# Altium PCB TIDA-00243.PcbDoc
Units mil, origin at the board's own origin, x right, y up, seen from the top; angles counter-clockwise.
Board outline 354.33 x 511.81 mil, 4 copper layers (Top Layer, MidLayer1, MidLayer2, Bottom Layer), stack 31.584 mil thick; 39 components, 21 nets, 112 pads, 89 vias.
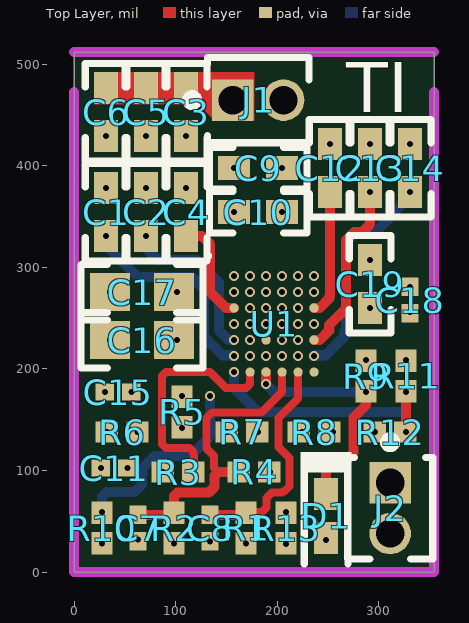
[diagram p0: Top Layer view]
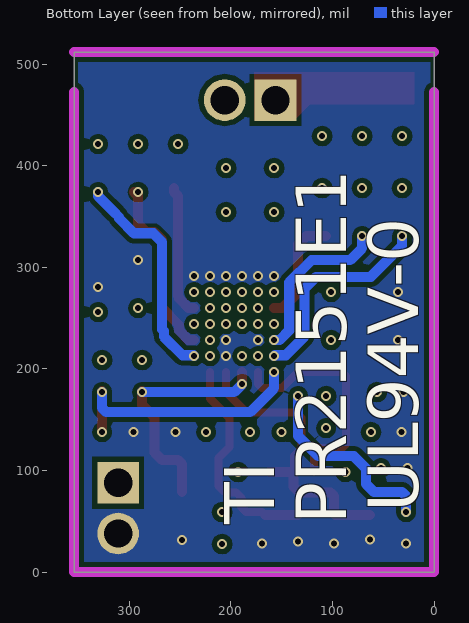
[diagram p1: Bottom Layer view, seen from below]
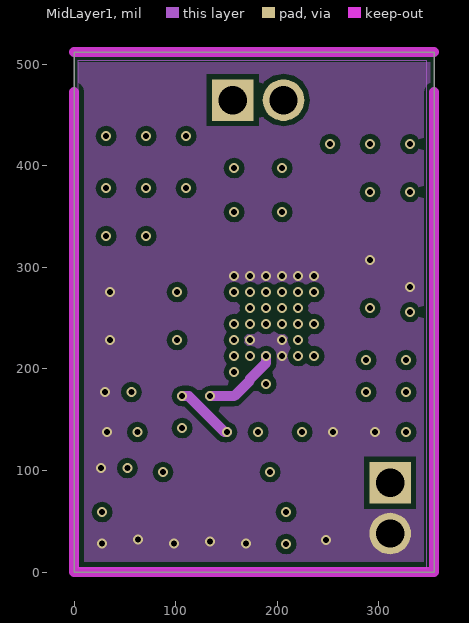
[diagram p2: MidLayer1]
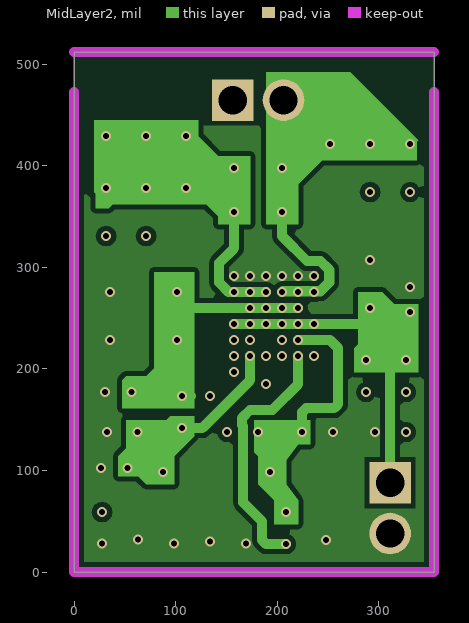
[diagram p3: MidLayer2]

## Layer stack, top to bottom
Top Layer: signal copper 1.4
Dielectric: core 8.6614, FR-4, Dk 4.8
MidLayer1: signal copper 1.4
Dielectric: prepreg 8.6614, FR-4, Dk 4.8
MidLayer2: signal copper 1.4
Dielectric: core 8.6614, FR-4, Dk 4.8
Bottom Layer: signal copper 1.4

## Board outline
0,0 0,511.81 354.33,511.81 354.33,0 0,0

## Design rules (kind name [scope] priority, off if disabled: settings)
AcuteAngle [All] p1: minimum=4.50000000000000E+0001 checktracksonly=FALSE
AssemblyTestPointUsage [All] p1: valid=2
Clearance Clearance_BoardEdge_MountingHoles [OnCopper and InComponentClass('Mounting Holes') vs IsKeepOut] p1: gap=4.92
Clearance Clearance_BoardEdge_Poly [OnCopper and InPoly vs IsKeepOut] p2: gap=4.92
Clearance Clearance_BoardEdge [OnCopper and Not InComponentClass('Logo') and not InComponentClass('FiducialMark') and not InRegion(1000,500,4000,800) and Not IsKeepout vs IsKeepOut] p3: gap=4.92
Clearance Clearance_Poly [InPolygon] p4: gap=4.92
Clearance [All] p5: gap=4.92
ComponentClearance ComponentClearance_Logo [InComponentClass('Logo')] p1: gap=4.92 collisioncheckmode=3 verticalgap=4.92 showdistances=FALSE
ComponentClearance ComponentClearance_ScrewToNut [(HasFootprint('NY PMS 440 0025 PH')) vs (HasFootprint('Keystone_1902C'))] p2: gap=4.92 collisioncheckmode=3 verticalgap=4.92 showdistances=FALSE
ComponentClearance ComponentClearance_MountingHoles [InComponentClass('Mounting Holes')] p3: gap=4.92 collisioncheckmode=3 verticalgap=100000 showdistances=FALSE
ComponentClearance ComponentClearance_SmallPassives [HasFootprint('0201*') or HasFootprint('0402*') or HasFootprint('0508') or HasFootprint('0603*') or HasFootprint('0612') or HasFootprint('0805*') or HasFootprint('0815*') or HasFootprint('0830*') or HasFootprint('1206*') or HasFootprint('1210*') or HasFootprint('1808*') or HasFootprint('1812*') or HasFootprint('1825*') or HasFootprint('2010*') or HasFootprint('2220*') or HasFootprint('2225*') or HasFootprint('2512*') or HasFootprint('2728*') or HasFootprint('3518*') vs HasFootprint('0201*') or HasFootprint('0402*') or HasFootprint('0508') or HasFootprint('0603*') or HasFootprint('0612') or HasFootprint('0805*') or HasFootprint('0815*') or HasFootprint('0830*') or HasFootprint('1206*') or HasFootprint('1210*') or HasFootprint('1808*') or HasFootprint('1812*') or HasFootprint('1825*') or HasFootprint('2010*') or HasFootprint('2220*') or HasFootprint('2225*') or HasFootprint('2512*') or HasFootprint('2728*') or HasFootprint('3518*')] p4: gap=4.92 collisioncheckmode=3 verticalgap=4.92 showdistances=FALSE
ComponentClearance ComponentClearance_THtoSMT [IsThruComponent vs IsSMTComponent] p5: gap=4.92 collisioncheckmode=3 verticalgap=4.92 showdistances=FALSE
ComponentClearance ComponentClearance_THtoTH [IsThruComponent vs IsThruComponent] p6: gap=4.92 collisioncheckmode=3 verticalgap=4.92 showdistances=FALSE
ComponentClearance [All] p7: gap=4.92 collisioncheckmode=3 verticalgap=4.92 showdistances=FALSE
DiffPairsRouting [All] p1: maxlimit=100 minlimit=10 mostfreqgap=10 maxuncoupledlength=1000
FabricationTestPointUsage TestPointUsage [All] p1: valid=2 allowmultiple=FALSE
FabricationTestpoint Testpoint [All] p1: side=3 testpointundercomponent=TRUE minsize=40 maxsize=100 preferedsize=60 minholesize=0 maxholesize=40 preferedholesize=32 testpointgrid=1 allowsidetop=TRUE allowsidebottom=TRUE usegrid=TRUE gridtolerance=0.01
FanoutControl Fanout_LCC [IsLCC] p1: bgadir=Out bgaviamode=Centered fanoutstyle=Auto fanoutdirection=Alternating viagrid=1 // Fanout_LCC (Default Rule)
FanoutControl Fanout_BGA [IsBGA] p2: bgadir=Out bgaviamode=Centered fanoutstyle=Auto fanoutdirection=Alternating viagrid=1 // Fanout_BGA (Default Rule)
FanoutControl Fanout_Default [All] p4: bgadir=Out bgaviamode=Centered fanoutstyle=Auto fanoutdirection=Alternating viagrid=1 // Fanout_Default (Default Rule)
FanoutControl Fanout_Small [(CompPinCount < 5)] p5: bgadir=Out bgaviamode=Centered fanoutstyle=Auto fanoutdirection=OutThenIn viagrid=1 // Fanout_Small (Default Rule)
HoleSize [All] p1: absolutevalues=TRUE maxlimit=251 minlimit=5 maxpercent=80.000 minpercent=20.000
HoleToHoleClearance [All] p1: gap=9 allowstackedmicrovias=TRUE
MinimumAnnularRing [All] p1: minimumring=4
MinimumSolderMaskSliver MinimumSolderMaskSliver_Logo [InComponentClass('Logo') vs InComponentClass('Logo')] p1: minsoldermaskwidth=0.7
MinimumSolderMaskSliver [All] p2: minsoldermaskwidth=4
PlaneClearance [All] p1: clearance=4.92
PlaneConnect [All] p1: planeconnectstyle=Direct reliefexpansion=10 reliefentries=4 reliefconductorwidth=10 reliefairgap=10
PolygonConnect [All] p1: connectstyle=Direct reliefconductorwidth=10 reliefentries=4 polygonreliefangle="90 Angle" airgapwidth=10
RoutingVias [All] p1: holewidth=16 width=34 viastyle="Through Hole" minholewidth=5 minwidth=9 maxholewidth=40 maxwidth=65
SMDToCorner [All] p1: distance=30000
SilkToSilkClearance [All] p1: silktosilkclearance=5
SilkscreenOverComponentPads [All] p1: minsilkscreentomaskgap=5
SolderMaskExpansion [All] p1: expansion=3
Width [All] p1: maxlimit=98.43 minlimit=4.92 preferedwidth=10 toplayer_prefwidth=7.87 midlayer1_minwidth=6 midlayer2_minwidth=6 bottomlayer_prefwidth=7.87 minimp=50.000000 maximp=50.000000 favimp=50.000000 checkconnectedcopper=TRUE
12 further rules are at their usual default settings.

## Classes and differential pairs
component class "PR2151 sheet 2": C1 C2 C3 C4 C5 C6 C7 C8 C9 C10 C11 C12 C13 C14 C15 C16 C17 C18 C19 D1 J1 J2 R1 R2 R3 R4 R5 R6 R7 R8 R9 R10 R11 R12 R13 U1
component class AssemblyNote: ZZ1 ZZ2 ZZ3
component class "PR2151 sheet 3": ZZ1 ZZ2 ZZ3

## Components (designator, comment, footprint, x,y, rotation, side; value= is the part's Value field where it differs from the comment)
C1 "C1005X7R1H683K" 0402 31.5,354.33 r90 top
C2 "UMK105ABJ474KV-F" 0402 70.87,354.33 r90 top
C3 "C1005X7R1H104K" 0402 110.24,452.76 r90 top
C4 "GRM155R71H153KA12D" 0402 110.24,354.33 r90 top
C5 "C1005X7R1H683K" 0402 70.87,452.76 r90 top
C6 "C1005X7R1H683K" 0402 31.5,452.76 r90 top
C7 "C0603X5R1E104K030BB" 0201 62.99,43.31 r270 top
C8 "CL03A105MP3NSNC" 0201 133.86,43.31 r270 top
C9 "GRM1555C1H101JA01D" 0402 181.1,397.64 r0 top
C10 "GRM155R71H272KA01J" 0402 181.1,354.33 r0 top
C11 "C0603X5R1E104K030BB" 0201 39.37,102.36 r180 top
C12 "GRM155R71H153KA12D" 0402 251.97,397.64 r90 top
C13 "UMK105ABJ474KV-F" 0402 291.34,397.64 r90 top
C14 "C1005X7R1H683K" 0402 330.71,397.64 r90 top
C15 "C0603X5R1E104K030BB" 0201 43.31,177.17 r180 top
C16 "GRM188R61E106MA73D" 0603 66.93,228.35 r180 top
C17 "GRM188R61E106MA73D" 0603 66.93,275.59 r180 top
C18 "C0603X5R1E104K030BB" 0201 330.71,267.72 r90 top
C19 "CGB2A1X5R1E105K033BC" 0402 291.34,283.46 r90 top
D1 "BZT52C5V1T-7" SOD-523 248.03,55.12 r270 top
J1 "GRPB021VWVN-RC" Sullins_GRPB021VWVN-RC 181.1,464.57 r0 top
J2 "GRPB021VWVN-RC" Sullins_GRPB021VWVN-RC 311.02,62.99 r270 top
R1 "ERJ-1GEF1004C" 0201M 169.29,43.31 r90 top
R2 "ERJ-1GEF1002C" 0201M 98.43,43.31 r90 top
R3 "ERJ-1GEF1100C" 0201M 102.36,98.43 r0 top
R4 "ERJ-1GEF2002C" 0201M 177.17,98.43 r180 top
R5 "ERJ-1GEF2002C" 0201M 106.3,157.48 r270 top
R6 "ERJ-1GEF4990C" 0201M 47.24,137.8 r0 top
R7 "ERJ-1GEF1023C" 0201M 165.35,137.8 r0 top
R8 "ERJ-1GEF1132C" 0201M 236.22,137.8 r180 top
R9 "ERJ-1GEF1002C" 0201M 287.4,192.91 r270 top
R10 "ERJ-1GEF1001C" 0201M 27.56,43.31 r90 top
R11 "ERJ-1GEF1023C" 0201M 326.77,192.91 r90 top
R12 "ERJ-1GEF1132C" 0201M 311.02,137.8 r0 top
R13 "ERJ-1GEF1132C" 0201M 208.66,43.31 r270 top
U1 "bq5102x" YFP0042AWCG 196.85,244.09 r0 top
ZZ1 "These assemblies are ESD sensitive, ESD precautions shall be observed." AssemblyNote 141.69,1242.5 r0 top
ZZ2 "These assemblies must be clean and free from flux and all contaminants. Use of no clean flux is not acceptable." AssemblyNote 141.69,1153.94 r0 top
ZZ3 "These assemblies must comply with workmanship standards IPC-A-610 Class 2., unless otherwise specified." AssemblyNote 141.69,1065.39 r0 top

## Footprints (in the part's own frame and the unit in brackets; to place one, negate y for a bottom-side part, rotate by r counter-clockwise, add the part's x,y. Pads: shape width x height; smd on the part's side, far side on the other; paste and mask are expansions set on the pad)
0201 [mm] "Data from Kemet datasheet CC101_COM dated 7/28/11"
  rect 0.46x0.42 smd mask+0.048: 1(-0.33,0) 2(0.33,0)
  body extent -0.31,-0.16 0.31,0.16, height 0.26
0201M [mm] "Data from Kemet datasheet CC101_COM dated 7/28/11"
  rect 0.56x0.52 smd mask+0.048: 1(-0.38,0) 2(0.38,0)
  body extent -0.31,-0.16 0.31,0.16, height 0.26
0402 [mm] "0402 from SM-752 data"
  rect 0.8x0.6 smd: 1(-0.6,0) 2(0.6,0)
  silkscreen extent -1.22,-0.52 1.22,0.52, body extent -0.55,-0.3 0.55,0.3, height 0.6
0603 [mm] "0603 from SM-752 data"
  rect 1x0.95 smd: 1(-0.8,0) 2(0.8,0)
  silkscreen extent -1.52,-0.69 1.52,0.69, body extent -0.87,-0.47 0.87,0.47, height 0.85
AssemblyNote [mil] "Assembly Note"
SOD-523 [mm] "NXP Semiconductor recommended land pattern, nominal STEP model"
  rect 0.8x0.6 smd paste-0.05: 1(-0.55,0) 2(0.55,0)
  silkscreen extent -1.6,-0.63 1.2,0.64, body extent -0.8,-0.4 0.8,0.4, height 0.72
Sullins_GRPB021VWVN-RC [mil] "Sullins"
  rect 41x41 hole 28: 1(-25,0)
  round 41 hole 28: 2(25,0)
  silkscreen extent -70,-42 50,42, body extent -50,-42 50,42, height 157
YFP0042AWCG [mm] "BGA, 42-Leads, Body 3.556x2.844mm,  Pitch 0.4mm"
  round 0.23 smd paste-0.2 mask+0.04: A1(-1,1.2) A2(-0.6,1.2) A3(-0.2,1.2) A4(0.2,1.2) A5(0.6,1.2) A6(1,1.2) B1(-1,0.8) B2(-0.6,0.8) B3(-0.2,0.8) B4(0.2,0.8) B5(0.6,0.8) B6(1,0.8) C1(-1,0.4) C2(-0.6,0.4) C3(-0.2,0.4) C4(0.2,0.4) C5(0.6,0.4) C6(1,0.4) D1(-1,0) D2(-0.6,0) D3(-0.2,0) D4(0.2,0) D5(0.6,0) D6(1,0) E1(-1,-0.4) E2(-0.6,-0.4) E3(-0.2,-0.4) E4(0.2,-0.4) E5(0.6,-0.4) E6(1,-0.4) F1(-1,-0.8) F2(-0.6,-0.8) F3(-0.2,-0.8) F4(0.2,-0.8) F5(0.6,-0.8) F6(1,-0.8) G1(-1,-1.2) G2(-0.6,-1.2) G3(-0.2,-1.2) G4(0.2,-1.2) G5(0.6,-1.2) G6(1,-1.2)
  silkscreen extent -1.7,1.65 -1.6,1.75, body extent -1.44,-1.8 1.44,1.8, height 0.51

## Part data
C1 C5 C6 C14: "CAP, CERM, 0.068uF, 50V, +/-10%, C0G/NP0, 0402"
C2 C13: library part GRM155R61A474KE15D, "CAP, CERM, 0.47uF, 50V, +/-10%, X5R, 0402"
C3: "CAP, CERM, 0.1uF, 50V, +/-10%, C0G/NP0, 0402"
C4 C12: "CAP, CERM, 0.015uF, 50V, +/-10%, X7R, 0402"
C7 C11 C15 C18: library part C0603X5R0J103K, "CAP, CERM, 0.1uF, 25V, +/-10%, X5R, 0201"
C8: "CAP, CERM, 1uF, 10V, +/-20%, X5R, 0201"
C9: "CAP, CERM, 100pF, 50V, +/-5%, C0G/NP0, 0402"
C10: library part GRM155R71H222KA01D, "CAP, CERM, 2700pF, 50V, +/-10%, X7R, 0402"
C16 C17: library part GRM188R61E105KA12D, "CAP, CERM, 10uF, 25V, +/-10%, X5R, 0603"
C19: library part GRM155R61A105KE15D, "CAP, CERM, 1uF, 25V, +/-10%, X5R, 0402"
D1: "Diode, Zener, 5.1V, 300mW, SOD-523"
J1 J2: "Header male, 2x1, 50mil, TH"
R1: library part ERJ-1GE0R00C, "RES, 1M0 ohm, 1%, 0.05W, 0201"
R2 R9: library part ERJ-1GE0R00C, "RES, 10k ohm, 1%, 0.05W, 0201"
R3: library part ERJ-1GE0R00C, "RES, 110 ohm, 1%, 0.05W, 0201"
R4 R5: library part ERJ-1GE0R00C, "RES, 20k ohm, 1%, 0.05W, 0201"
R6: library part CRCW0201499RFKED, "RES, 499 ohm, 1%, 0.05W, 0201"
R7 R11: library part ERJ-1GE0R00C, "RES, 102k ohm, 1%, 0.05W, 0201"
R8 R12 R13: library part ERJ-1GE0R00C, "RES, 11.3k ohm, 1%, 0.05W, 0201"
R10: library part ERJ-1GE0R00C, "RES, 1.00k ohm, 1%, 0.05W, 0201"
U1: library part bq51221YFP, "DUAL MODE (Qi and PMA) INTEGRATED WIRELESS RECEIVER POWER SUPPLY, YFP0042AWCG"
ZZ1 ZZ2 ZZ3: library part AssemblyNote

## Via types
v1: diameter 9.84, hole 5.91, Top Layer to Bottom Layer, 89 vias

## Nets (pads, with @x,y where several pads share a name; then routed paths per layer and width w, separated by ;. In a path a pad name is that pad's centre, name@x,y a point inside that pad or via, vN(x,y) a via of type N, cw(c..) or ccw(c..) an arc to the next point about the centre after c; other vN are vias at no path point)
GND: C7.2 C8.2 C11.2 C15.2 C16.2 C17.2 C18.2 C19.2 D1.2 J2.2 R1.1 R2.1 R6.1 R8.1 R10.1 R12.1 U1.A1 U1.A2 U1.A3 U1.A4 U1.A5 U1.A6 U1.E2 U1.E4 U1.F4
  other v1: 27.56,28.35 98.43,28.35 169.29,28.35 133.86,30.32 248.03,31.5 62.99,32.28 26.38,102.36 32.28,137.8 254.72,137.8 296.06,137.8 30.32,177.17 204.72,212.6 35.43,228.35 173.23,228.35 204.72,228.35 35.43,275.59 330.71,280.71 157.48,291.34 173.23,291.34 188.98,291.34 204.72,291.34 220.47,291.34 236.22,291.34 291.34,307.09
NetC1_1: C1.1 U1.F1 | length 208
  Bottom Layer w10: v1(31.5,330.71) 31.5,321.42 62.3,290.61 116.11,290.61 127.72,279.01 127.72,231.77 146.06,213.43 156.65,213.43 v1(157.48,212.6)
NetC1_2: C1.2 C2.2 C3.1 C4.2 C5.1 C6.1 C9.1 C10.1 U1.B1 U1.B2 U1.B3 | length 125.6
  MidLayer2 w10: v1(157.48,354.33) 157.48,318.9 142.64,304.05 142.64,285.19 152.24,275.59 v1(157.48,275.59) v1(173.23,275.59) v1(188.98,275.59)
  other v1: 31.5,377.95 70.87,377.95 110.24,377.95 157.48,397.62 31.5,429.13 70.87,429.13 110.24,429.13
NetC2_1: C2.1 U1.E1 | length 163.6
  Bottom Layer w10: v1(70.87,330.71) 70.87,318.9 82.68,307.09 120.74,307.09 142.64,285.19 142.64,237.95 152.24,228.35 v1(157.48,228.35)
NetC3_2: C3.2 C5.2 C6.2 J1.1
NetC4_1: C4.1 U1.C1 | length 108.2
  Top Layer w10: C4.1@106.3,330.71 C4.1 125.98,330.71 133.86,322.83 133.86,275.59 149.61,259.84 U1.C1
NetC7_1: C7.1 R2.2 R4.2 U1.G4 | length 291.6
  Top Layer w8: 141.73,98.43 137.8,102.36 137.8,114.17 130.45,121.52 130.45,151.73 135.67,156.95 184.51,156.95 204.72,177.17 U1.G4
  Top Layer w10: C7.1 R2.2@97.24,56.3 ; R2.2@98.43,59.06 98.43,74.8 101.89,78.27 132.46,78.27 138.27,84.08 138.27,94.96 141.73,98.43 R4.2@161.42,98.43
NetC8_1: C8.1 R1.2 U1.G5 | length 216.3
  Top Layer w8: R1.2@169.29,59.06 185.04,59.06 189.5,63.52 189.5,72.99 194.73,78.21 204.2,78.21 205.25,79.27 206.84,79.27 212.07,84.49 212.07,112.36 201.32,123.11 201.32,151.73 220.47,170.88 U1.G5
  Top Layer w10: C8.1 R1.2@166.54,56.3
NetC9_2: C9.2 C10.2 C12.2 C13.2 C14.2 J1.2 U1.B4 U1.B5 U1.B6 | length 146.3
  MidLayer2 w10: v1(204.72,275.59) 205.63,276.5 242.37,276.5 251.06,285.19 251.06,297.49 242.37,306.18 229.25,306.18 204.72,330.71 v1(204.72,354.33)
  other v1: 220.47,275.59 236.22,275.59 204.72,397.64 251.97,421.26 291.34,421.26 330.71,421.26
NetC11_1: C11.1 R3.1 R5.2 R6.2 U1.F2 | length 110.1
  MidLayer2 w10: v1(106.3,141.73) 125.98,141.73 173.23,188.98 v1(173.23,212.6)
  other v1: 87.4,98.43 52.36,102.36 62.2,137.8
NetC12_1: C12.1 U1.C6 | length 129.3
  Top Layer w10: U1.C6 241.46,259.84 251.06,269.44 251.06,270.75 251.97,271.65 251.97,370.08 255.91,374.02 C12.1@255.91,377.95
NetC13_1: C13.1 U1.E6 | length 177.8
  Top Layer w10: U1.E6 241.46,228.35 251.06,237.95 251.06,243.19 267.72,259.84 267.72,326.77 275.59,334.65 283.46,334.65 291.34,342.52 291.34,370.08 C13.1@295.28,374.02
  other v1: 291.34,374.02
NetC14_1: C14.1 U1.F6 | length 218
  Bottom Layer w10: v1(236.22,212.6) 237.05,213.43 247.64,213.43 265.98,231.77 265.98,237.01 267.72,238.74 267.72,324.8 276.42,333.5 295.55,333.5 310.2,348.15 310.2,349.57 315.32,354.69 325.58,364.95 330.71,370.08 v1(330.71,374.02)
NetC15_1: C15.1 C16.1 C17.1 R5.1 R7.1 U1.C2 U1.C3 U1.C4 U1.C5 | length 202.3
  MidLayer1 w10: v1(106.3,173.23) 112.76,173.23 148.19,137.8 v1(150.39,137.8)
  MidLayer2 w10: v1(101.36,275.59) 101.38,259.84 v1(173.23,259.84) v1(188.98,259.84) v1(204.72,259.84) v1(220.47,259.84) ; v1(106.3,173.23) 114.96,173.23
  other v1: 56.3,177.17 101.38,228.35
NetC18_1: C18.1 C19.1 J2.1 R9.1 R11.2 U1.D1 U1.D2 U1.D3 U1.D4 U1.D5 U1.D6 | length 273.3
  MidLayer2 w10: v1(157.48,244.09) v1(173.23,244.09) v1(188.98,244.09) v1(204.72,244.09) v1(220.47,244.09) v1(236.22,244.09) 251.97,244.09 291.34,244.09 v1(291.34,259.84) ; 307.09,208.66 311.02,204.72 J2.1 J2.1@311.02,86.61
  other v1: 287.4,208.66 326.77,208.66 330.71,255.91
NetD1_1: D1.1 R9.2 U1.G3 | length 238.2
  Top Layer w10: v1(188.98,185.04) U1.G3 ; D1.1@248.03,78.74 248.03,106.3 251.97,110.24 267.72,110.24 275.12,117.64 275.12,152.14 287.4,164.42 v1(287.4,177.17) R9.2
  Bottom Layer w10: v1(188.98,185.04) 196.85,177.17 v1(287.4,177.17)
NetR3_2: R3.2 U1.G2 | length 229.2
  Top Layer w8: R3.2@118.11,98.43 118.11,115 117.53,115.58 117.53,118.11 113.59,122.05 90.55,122.05 86.61,125.98 86.61,192.91 90.55,196.85 133.86,196.85 149.61,181.1 169.29,181.1 173.23,185.04 U1.G2
NetR4_1: R4.1 R7.2 R8.2 R13.1 U1.E5 | length 160.1
  MidLayer2 w10: v1@220.47,137.8 v1(224.41,137.8) 224.41,157.48 228.35,161.42 255.91,161.42 259.84,165.35 259.84,220.47 251.97,228.35 v1(220.47,228.35)
  other v1: 208.66,59.06 192.91,98.43 181.1,137.8
NetR10_2: R10.2 U1.F3 | length 271
  MidLayer1 w10: v1(133.86,173.23) 157.48,173.23 173.23,188.98 173.23,190.28 188.98,206.03 v1(188.98,212.6)
  Bottom Layer w10: v1(27.56,59.06) 27.56,74.8 31.5,78.74 59.06,78.74 66.93,86.61 66.93,95.66 67.2,95.94 67.2,102.36 79.02,114.17 114.17,114.17 133.86,133.86 v1(133.86,173.23)
NetR11_1: R11.1 R12.2 U1.G1 | length 252.4
  Top Layer w10: v1(326.77,137.8) R11.1
  Bottom Layer w10: v1(157.48,196.85) 157.48,181.1 181.1,157.48 322.83,157.48 326.77,161.42 v1(326.77,177.17)
NetR13_2: R13.2 U1.F5 | length 250.2
  MidLayer2 w10: v1(208.66,27.56) 188.98,27.56 185.04,31.5 185.04,49.87 166.26,68.65 166.26,143.94 165.35,144.85 165.35,151.83 173.06,159.53 194.96,159.53 220.47,185.04 v1(220.47,212.6)
pads on no net: U1.E3 U1.G6
copper on no net: | length 11145.8
  Top Layer w3.94: 11371.02,7523.62 13719.53,7523.62 ; 11371.02,7608.27 13719.53,7608.27 ; 11311.02,6964.57 ccw(c11338.58,6964.57) 11338.58,6937.01 13751.97,6937.01 ccw(c13751.97,6964.57) 13779.53,6964.57 13779.53,7688.98 ccw(c13751.97,7688.98) 13751.97,7716.54 11338.58,7716.54 ccw(c11338.58,7688.98) 11311.02,7688.98 11311.02,6964.57

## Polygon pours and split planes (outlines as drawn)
GND on MidLayer1 "MidLayer1-GND" (solid, shelved, pour order 8): 3.94,3.94 3.94,503.94 346.46,503.94 346.46,3.94 3.94,3.94
GND on MidLayer1 "MidLayer1-No Net" (solid, remove dead copper, pour order 3): 3.94,3.94 3.94,507.87 350.39,507.87 350.39,3.94 3.94,3.94
GND on MidLayer2 "MidLayer2-No Net" (solid, remove dead copper, pour order 5): 3.94,3.94 3.94,507.87 350.39,507.87 350.39,3.94 3.94,3.94
GND on Bottom Layer "Bottom Layer-No Net" (solid, remove dead copper, pour order 7): 3.94,3.94 3.94,507.87 350.39,507.87 350.39,3.94 3.94,3.94

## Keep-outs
Keep-Out Layer:
  lines w10: 0,472.44 0,0 354.33,0 354.33,472.44 ; 0,511.81 354.33,511.81 ; 4950,3455 cw(c4950,3450) 4955,3450 ; 4950,3455 cw(c4950,3450) 4955,3450 ; 4950,3455 cw(c4950,3450) 4955,3450 ; 4950,3455 cw(c4950,3450) 4955,3450 ; 4950,3455 cw(c4950,3450) 4955,3450 ; 4950,3455 cw(c4950,3450) 4955,3450
  text ".Layer_Name" at 577,-858.49 h60

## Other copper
Top Layer:
  region net NetC3_2: 19.68,492.13 177.17,492.13 177.17,444.88 137.8,444.88 122.05,460.63 19.68,460.63
  text "Layer Stack Up Detail for: PR2151.PcbDoc" at 11371.02,7631.3 h41.34
  text "Layer" at 11371.02,7576.77 h19.68
  text "Gerber" at 12189.14,7576.77 h19.68
  text "Copper" at 12744.09,7576.77 h19.68
  text "Dielectric" at 13331.17,7576.77 h19.68
  text "Name" at 11371.02,7537.4 h19.68
  text "Document" at 12189.14,7537.4 h19.68
  text "Thickness" at 12744.09,7537.4 h19.68
  text "Material" at 13331.17,7537.4 h19.68
  text "Top Solder Mask" at 11371.02,7481.05 h27.56
  text "(.GTS)" at 12189.14,7481.05 h27.56
  text "Solder Resist" at 13331.17,7481.05 h27.56
  text "Top Layer" at 11371.02,7399.85 h27.56
  text "(.GTL)" at 12189.14,7399.85 h27.56
  text "0.0356mm" at 12744.09,7399.85 h27.56
  text "FR-4" at 13331.17,7359.25 h27.56
  text "MidLayer1" at 11371.02,7318.65 h27.56
  text "(.G1)" at 12189.14,7318.65 h27.56
  text "0.0356mm" at 12744.09,7318.65 h27.56
  text "FR-4" at 13331.17,7278.05 h27.56
  text "MidLayer2" at 11371.02,7237.45 h27.56
  text "(.G2)" at 12189.14,7237.45 h27.56
  text "0.0356mm" at 12744.09,7237.45 h27.56
  text "FR-4" at 13331.17,7196.85 h27.56
  text "Bottom Layer" at 11371.02,7156.25 h27.56
  text "(.GBL)" at 12189.14,7156.25 h27.56
  text "0.0356mm" at 12744.09,7156.25 h27.56
  text "Bottom Solder Mask" at 11371.02,7075.05 h27.56
  text "(.GBS)" at 12189.14,7075.05 h27.56
  text "Solder Resist" at 13331.17,7075.05 h27.56
  text ".Layer_Name" at 577,-858.49 h60
MidLayer2:
  region net NetC1_2: 19.68,444.88 122.05,444.88 122.05,429.13 141.73,409.45 173.23,409.45 173.23,342.52 141.73,342.52 141.73,350.39 129.92,362.2 37.99,362.2 34.06,358.27 21.06,358.27 21.08,364.76 21.06,372.64 19.68,374.02
  region net NetC9_2: 188.98,342.52 188.98,492.13 271.65,492.13 338.58,425.2 337.2,423.82 337.2,405.51 244.09,405.51 220.47,381.89 220.47,342.52
  region net NetC18_1: 279.53,275.59 279.53,224.41 275.59,220.47 275.59,196.85 338.58,196.85 338.58,263.78 314.96,263.78 303.15,275.59
  region net NetC15_1: 118.11,295.28 118.11,161.42 47.24,161.42 47.24,188.98 51.18,192.91 70.87,192.91 78.74,200.79 78.74,295.28
  region net NetR4_1: 177.17,149.61 232.28,149.61 232.28,125.98 220.47,125.98 208.66,110.24 208.66,86.61 220.47,70.87 220.47,47.24 196.85,47.24 196.85,70.87 181.1,86.61 181.1,114.17 177.17,118.11
  region net NetC11_1: 51.18,149.61 90.55,149.61 94.49,153.54 118.11,153.54 118.11,133.86 98.43,114.17 98.43,86.61 70.87,86.61 62.99,94.49 43.31,94.49 43.31,114.17 51.18,122.05
Bottom Layer:
  text ".Layer_Name" at 577,-858.49 h60

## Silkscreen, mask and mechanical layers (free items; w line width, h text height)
Top Overlay:
  text "TI" at 267.72,452.76 h49.21
  text ".Layer_Name" at 577,-858.49 h60
Bottom Overlay:
  text "UL94V-0" at 15.75,59.06 h50 r270
  text "PR2151E1" at 86.61,47.24 h50 r270
  text "TI" at 157.48,47.24 h49.21 r270
  text ".Layer_Name" at 577,-858.49 h60
Top Paste:
  text ".Layer_Name" at 577,-858.49 h60
Bottom Paste:
  text ".Layer_Name" at 577,-858.49 h60
Top Solder:
  text ".Layer_Name" at 577,-858.49 h60
  text ".Layer_Name" at 577,-858.49 h60
Bottom Solder:
  text ".Layer_Name" at 577,-858.49 h60
Drill Guide:
  text ".Layer_Name" at 577,-858.49 h60
M1 Board Outline:
  the board outline again, w10
  text ".Layer_Name" at 577,-858.49 h60
M2 Board Dimensions:
  rectangle: 124.5,-410.5 499.5,-285.5
  rectangle: -0.5,-285.5 124.5,-160.5
  lines w7: -0.5,-285.5 999.5,-285.5 ; 124.5,-410.5 124.5,-160.5 ; 249.5,-410.5 249.5,-160.5 ; 499.5,-410.5 499.5,-160.5 ; 749.5,-410.5 749.5,-160.5 ; -0.5,-410.5 -0.5,-160.5 999.5,-160.5 999.5,-410.5 -0.5,-410.5
  lines w10: -0.5,-475.5 -0.5,-455.5 ; 59.5,-485.5 -0.5,-465.5 ; 59.5,-445.5 -0.5,-465.5 ; 243.58,-465.5 -0.5,-465.5 ; 755.42,-465.5 999.5,-465.5 ; 939.5,-485.5 999.5,-465.5 ; 939.5,-445.5 999.5,-465.5 ; 999.5,-475.5 999.5,-455.5
  text "25.4 (mm)" at 253.58,-501.49 h60
  text ".Layer_Name" at 577,-858.49 h60
M3 3D STEP Top:
  text ".Layer_Name" at 577,-858.49 h60
M4 3D STEP Bottom:
  text ".Layer_Name" at 577,-858.49 h60
M5 Assembly Top:
  lines w7: 5139,110.5 6264,110.5 ; 5139,233 6261.5,233 ; 5454,-9.5 5454,353 ; 5839,-9.5 5139,-9.5 ; 5839,353 5139,353 ; 5139,-9.5 5139,353 ; 5139,-9.5 6264,-9.5 6264,353 5139,353
  lines w10: -292,-930.17 6308,-930.17 ; -292,-726.83 6310,-726.83 ; -292,-523.5 -292,-1133.5 3713,-1133.5 6310,-1133.5 6310,-523.5 -291.5,-523.5 -291.5,-1133.5 1284,-1133.5 ; 2173,-1133.5 2173,-523.5 ; 3440,-726.83 3440,-523.5 ; 4280,-726.83 4280,-523.5 ; 4902,-1140 4902,-937.17
  text "TABLE 1" at 5526.5,388 h40
  text "Variant" at 5164,278 h40
  text "Label text" at 5599,278 h40
  text "001" at 5231.5,158 h40
  text "ChangeMe!" at 5509,155.5 h40
  text "002" at 5231.5,33 h40
  text "ChangeMe!" at 5504,30.5 h40
  text "COMPONENTS MARKED 'DNP' SHOULD NOT BE POPULATED." at 1153.5,-318.5 h60
  text "ASSEMBLY VARIANT:" at 1153,-434 h60
  text ".VariantName" at 2189,-434 h60
  text "PCB VIEWED FROM TOP SIDE" at -228.5,-655.67 h60
  text "BOARD #:" at 2248,-655.67 h60
  text ".PRJ_Number" at 2793.5,-655.67 h60
  text "REV:" at 3638,-655.67 h60
  text ".PCB_Rev" at 3929.5,-655.67 h60
  text "SVN REV:" at 4476,-655.67 h60
  text ".VersionControl_RevNumber" at 4982,-655.67 h60
  text "IGNORE ->" at -228.5,-858.49 h60
  text "PLOT NAME =" at -228.5,-1064.34 h60
  text ".plot_File_Name" at 577,-1064.34 h60
  text "GENERATED    :" at 2250,-1064.34 h60
  text ".Print_Date" at 3119.5,-1064.34 h60
  text ".Print_Time" at 3848.5,-1064.34 h60
  text "TEXAS INSTRUMENTS" at 5113,-1064.34 h60
M6 Assembly Bottom:
  lines w10: -292.5,-727.33 6309.5,-727.33 ; -290.5,-930.67 6309.5,-930.67 ; 1115.5,-1140.5 1115.5,-937.67 ; 1737.5,-727.33 1737.5,-524 ; 2577.5,-727.33 2577.5,-524 ; 3844.5,-1134 3844.5,-524 ; 4733.5,-1134 6309,-1134 6309,-524 -292.5,-524 -292.5,-1134 2304.5,-1134 6309.5,-1134 6309.5,-524
  text "COMPONENTS MARKED 'DNP' SHOULD NOT BE POPULATED." at 6102,-318 h60
  text ".VariantName" at 5058,-434 h60
  text "ASSEMBLY VARIANT:" at 6097,-434 h60
  text ".VersionControl_RevNumber" at 1035.5,-656.17 h60
  text "SVN REV:" at 1541.5,-656.17 h60
  text ".PCB_Rev" at 2088,-656.17 h60
  text "REV:" at 2379.5,-656.17 h60
  text ".PRJ_Number" at 3224,-656.17 h60
  text "BOARD #:" at 3769.5,-656.17 h60
  text "PCB VIEWED FROM BOTTOM SIDE" at 6246,-656.17 h60
  text "IGNORE ->" at 2547.85,-858.49 h60
  text "TEXAS INSTRUMENTS" at 904.5,-1064.84 h60
  text ".Print_Time" at 2169,-1064.84 h60
  text ".Print_Date" at 2898,-1064.84 h60
  text "GENERATED    :" at 3767.5,-1064.84 h60
  text ".plot_File_Name" at 5440.5,-1064.84 h60
  text "PLOT NAME =" at 6246,-1064.84 h60
M9 Title Sheet:
  drawing of 57 lines, arcs and shapes, not listed
  text "1" at 739.84,8036.5 h70
  text "2" at 3235.5,8036.5 h70
  text "3" at 5724.84,8036.5 h70
  text "4" at 8231.51,8036.5 h70
  text "5" at 10730.5,8036.5 h70
  text "6" at 13235.5,8036.5 h70
  text "A" at -416.5,6893.5 h70
  text "A" at 14383.5,6893.5 h70
  text "B" at -416.5,4513.5 h70
  text "B" at 14383.5,4513.5 h70
  text "C" at -416.5,2138.5 h70
  text "C" at 14383.5,2138.5 h70
  text "PROJECT TITLE:" at 11343.5,277.5 h45
  text ".PRJ_Title" at 11393.5,144.17 h70
  text "DESIGNED FOR:" at 11343.5,-23.5 h45
  text ".PRJ_Customer" at 11393.5,-163.5 h70
  text "D" at -416.5,-231.5 h70
  text "D" at 14383.5,-231.5 h70
  text "FILE NAME:" at 11343.5,-323.5 h45
  text ".PCB_File_Name_No_Path" at 11393.5,-443.5 h70
  text "Texas Instruments (TI) and/or its licensors do not warrant the accuracy or completeness of this specification" at 6374,-605.34 h45
  text "ENGINEER:" at 11343.5,-613.5 h45
  text "LAYOUT BY:" at 12848.5,-613.5 h45
  text "or any information contained therein. TI and/or its licensors do not warrant that this design will meet" at 6329.01,-718 h45
  text ".PRJ_Engineer" at 11393.5,-768.49 h70
  text ".PCB_Layout" at 12899,-768.49 h70
  text "the specifications, will be suitable for your application or fit for any particular purpose, or will operate in" at 6329.01,-830.67 h45
  text ".Layer_Name" at 577,-858.49 h60
  text "ALTIUM DESIGNER VERSION:" at 12848.5,-923.5 h45
  text "an implementation. TI and/or its licensors do not warrant that the design is production worthy. You should" at 6329.01,-943.33 h45
  text "completely validate and test your design implementation to confirm the system functionality for your application." at 6374,-1056 h45
  text ".print_Scale" at 11393.5,-1056.83 h70
  text ".Application_BuildNumber" at 12899,-1056.83 h70
  text "1" at 739.84,-1263.5 h70
  text "2" at 3235.5,-1263.5 h70
  text "3" at 5724.84,-1263.5 h70
  text "4" at 8231.51,-1263.5 h70
  text "5" at 10730.5,-1263.5 h70
  text "6" at 13235.5,-1263.5 h70
M10 Fab Notes:
  drawing of 212 lines, arcs and shapes, not listed
  text "DESIGN INFORMATION" at 12381.02,6810 h60
  text "(REFER ALSO ARRAY/PANEL PROFILING INFORMATION)" at 12019.46,6648.29 h60
  text "BOARD SIZE" at 11333.46,6644 h60
  text "13mm" at 11795.78,6516.18 h60
  text "X" at 12301.46,6516.18 h60
  text "9mm" at 12532.78,6516.18 h60
  text "Number of Layers :" at 11736.46,6319 h60
  text "4" at 12831.27,6309 h60
  text "MIN. TRACK WIDTH:" at 11736.46,6180 h60
  text "6" at 12832.7,6180 h60
  text "MIL" at 12987.46,6180 h60
  text "MIN. CLEARANCE:" at 11736.46,6048 h60
  text "6" at 12832.7,6048 h60
  text "MIL" at 12987.46,6048 h60
  text "MIN. VIA PAD SIZE:" at 11736.46,5916 h60
  text "10" at 12802.71,5916 h60
  text "MIL" at 12987.46,5916 h60
  text "0.05mm (2MIL)" at 12431.46,5774.29 h60
  text "MINIMUM ANNULAR RING" at 11407.23,5770 h60
  text "EXTERNAL" at 13139.46,5770 h60
  text "PER" at 11607.23,5652 h60
  text "IPC-D-275 CLASS 2 LEVEL C" at 11827.23,5652 h60
  text "MIL, HOLES" at 13315.46,5539.71 h60
  text "+/-" at 12923,5539 h60
  text "+/-" at 13777,5539 h60
  text "REGISTRATION TOLERANCES:" at 11407.23,5534 h60
  text "METAL" at 12607,5534 h60
  text "5" at 13183.2,5534 h60
  text "3" at 14016.2,5534 h60
  text "MIL" at 14132.46,5534 h60
  text "MATERIAL:" at 11332.46,5324.54 h60
  text "FR-4 High Tg" at 12318.9,5184.21 h60
  text "FR-408" at 11753.46,5175.64 h60
  text "X" at 12165.46,5175.64 h60
  text "OTHER" at 13241.46,5175.64 h60
  text "62 MIL (1.6mm) +/-10%" at 12073.56,5012.92 h60
  text "THICKNESS:" at 11407.23,5008.64 h60
  text "OTHER" at 13358.46,5008.64 h60
  text "X" at 13236.22,5003.94 h60
  text "32MIL +/-10%" at 13669.29,5003.94 h60
  text "TOLERANCE:" at 11407.23,4850.64 h60
  text "X" at 12246.53,4850.64 h60
  text "ANSI IPC-6012 TYPE 3 CLASS 2" at 12433.48,4850.64 h60
  text "OTHER +/-" at 12433.46,4694.64 h60
  text "BOW & TWIST:" at 11407.23,4537.64 h60
  text "X" at 12246.53,4537.64 h60
  text "ANSI IPC-6012 TYPE 3 CLASS 2" at 12433.48,4537.64 h60
  text "OTHER +/-" at 12433.46,4379.13 h60
  text "COPPER THICKNESS (FINISHED):" at 11332.46,4243.64 h60
  text "1.4MIL (1oz)" at 12212.46,4090.92 h60
  text "2MIL (1.4oz)" at 12979.46,4090.92 h60
  text "2.8MIL (2oz)" at 13706.46,4090.92 h60
  text "OUTER:" at 11689.46,4086.64 h60
  text "X" at 12084,4086 h60
  text "1.4MIL (1oz)" at 12212.46,3933.92 h60
  text "2.8MIL (2oz)" at 12979.46,3933.92 h60
  text "N/A" at 13706,3934.29 h60
  text "INNER SIGNAL:" at 11400.38,3929.64 h60
  text "X" at 12085.42,3929.64 h60
  text "DRILLING:" at 11332.46,3790.64 h60
  text "REFERENCE:" at 11407.23,3673.64 h60
  text "X" at 12055.46,3673.64 h60
  text "AS SHOWN" at 12242.46,3673.64 h60
  text "X" at 12956.46,3673.64 h60
  text "NC_DRILL FILES" at 13093.46,3673.64 h60
  text "PTH MIN COPPER THICKNESS:" at 11407.23,3515.64 h60
  text "X" at 12757.46,3515.64 h60
  text "1MIL" at 12894.46,3515.64 h60
  text "OTHER" at 13391.46,3515.64 h60
  text "BOARD FINISH:" at 11332.46,3356.64 h60
  text "SILKSCREEN:" at 11487.68,3238.64 h60
  text "X" at 12436.46,3238.64 h60
  text "TOP" at 12562.46,3238.64 h60
  text "X" at 12946.46,3238.64 h60
  text "BOTTOM" at 13073.46,3238.64 h60
  text "SILKSCREEN COLOR:" at 11487.68,3071.64 h60
  text "X" at 12435.42,3071.64 h60
  text "WHITE" at 12562.46,3071.64 h60
  text "OTHER" at 13073.46,3071.64 h60
  text "SOLDER RESIST COLOR:" at 11487.68,2901.64 h60
  text "X" at 12055.42,2742.44 h60
  text "GREEN" at 12182.46,2742.44 h60
  text "BLUE" at 12773.46,2742.44 h60
  text "OTHER" at 13311.46,2742.44 h60
  text "IMMERSION GOLD (ENIG)" at 12393.46,2553.92 h60
  text "ENEPIG" at 13731,2550.64 h60
  text "SURFACE FINISH:" at 11332.46,2549.64 h60
  text "X" at 12206.51,2549.64 h60
  text "IMM. TIN/SILVER OR EQUIV" at 11662,2392.64 h60
  text "OTHER" at 13093.46,2392.64 h60
  text "ARRAY/PANEL:" at 11332.46,2213.64 h60
  text "CUT AND TRIM PER MECH LAYER 1" at 12393.46,2209.35 h60
  text "N.C. ROUTE" at 12393.46,2057.64 h60
  text "V. SCORE" at 13259.46,2057.64 h60
  text "X" at 12196.85,2051.18 h60
  text "CERTIFICATION:" at 11332.46,1920.64 h60
  text "MATERIALS AND WORKMANSHIP FOR ALL PCBS" at 12057.46,1920.64 h60
  text "TO MEET OR EXCEED THE REQUIREMENTS OF:" at 12057.46,1822.64 h60
  text "X" at 11683.96,1686.13 h60
  text "ANSI IPC-A-600F CLASS ->" at 11822.96,1686.13 h60
  text "X" at 13462.02,1686.13 h60
  text "2" at 13580.96,1686.14 h60
  text "1" at 13265.96,1684.64 h60
  text "3" at 13934.96,1684.64 h60
  text "X" at 11686.02,1526.64 h60
  text "UL 94V-0" at 11822.96,1526.64 h60
  text "X" at 12498.02,1526.64 h60
  text "RoHS" at 12634.96,1526.64 h60
  text "OTHER" at 13279.36,1526.64 h60
  text "PER ORDER" at 13676.42,1526.64 h60
  text "ADDITIONAL REQUIREMENTS:" at 11332.46,1385.64 h60
  text "MICROSECTION:" at 11407.23,1270.64 h60
  text "YES" at 12312.96,1270.64 h60
  text "REQUIRED" at 13174.46,1114.49 h60
  text "BARE BOARD ELEC. TEST:" at 11407.23,1111.64 h60
  text "NONE" at 12712.96,1111.64 h60
  text "X" at 13047.46,1111.64 h60
  text "PER ORDER" at 13766.46,1111.64 h60
  text "MANUFACTURER'S UL:" at 11407.23,954.64 h60
  text "RAIL" at 12572.96,950.35 h60
  text "METAL" at 13064.77,950.35 h60
  text "X" at 13440,950 h60
  text "SILK" at 13576.46,950.35 h60
  text ".Layer_Name" at 577,-858.49 h60
M11 Gerber Information:
  lines w10: -292,-930.17 6308,-930.17 ; -292,-726.83 6310,-726.83 ; -292,-523.5 -292,-1133.5 3713,-1133.5 6310,-1133.5 6310,-523.5 -291.5,-523.5 -291.5,-1133.5 1284,-1133.5 ; 2173,-1133.5 2173,-523.5 ; 3440,-726.83 3440,-523.5 ; 4280,-726.83 4280,-523.5 ; 4902,-1140 4902,-937.17
  text "ALL ARTWORK VIEWED FROM TOP SIDE" at -228.5,-655.67 h60
  text "BOARD #:" at 2248,-655.67 h60
  text ".PRJ_Number" at 2793.5,-655.67 h60
  text "REV:" at 3638,-655.67 h60
  text ".PCB_Rev" at 3929.5,-655.67 h60
  text "SVN REV:" at 4476,-655.67 h60
  text ".VersionControl_RevNumber" at 4982,-655.67 h60
  text "LAYER NAME =" at -228.5,-858.49 h60
  text "PLOT NAME =" at -228.5,-1064.34 h60
  text ".plot_File_Name" at 577,-1064.34 h60
  text "GENERATED    :" at 2250,-1064.34 h60
  text ".Print_Date" at 3119.5,-1064.34 h60
  text ".Print_Time" at 3848.5,-1064.34 h60
  text "TEXAS INSTRUMENTS" at 5113,-1064.34 h60
M12 Stackup:
  text "The Stackup Legend below this is static." at 11605.5,7874.5 h60
  text "If you change the stackup, update the Legend." at 11615.5,7784.5 h60
  text ".Layer_Name" at 577,-858.49 h60
M13 Component Bodies Top:
  text ".Layer_Name" at 577,-858.49 h60
M14 Component Bodies Bottom:
  text ".Layer_Name" at 577,-858.49 h60
M15 Courtyards Top:
  text ".Layer_Name" at 577,-858.49 h60
M16 Courtyards Bottom:
  text ".Layer_Name" at 577,-858.49 h60
Drill Drawing:
  text ".legend" at 5122.5,725.5 h60
  text "Drill Table" at 5147.5,540.5 h60
  text ".Layer_Name" at 577,-858.49 h60

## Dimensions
354.33,0 to 0,0 on M2 Board Dimensions
0,511.81 to 0,0 on M2 Board Dimensions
